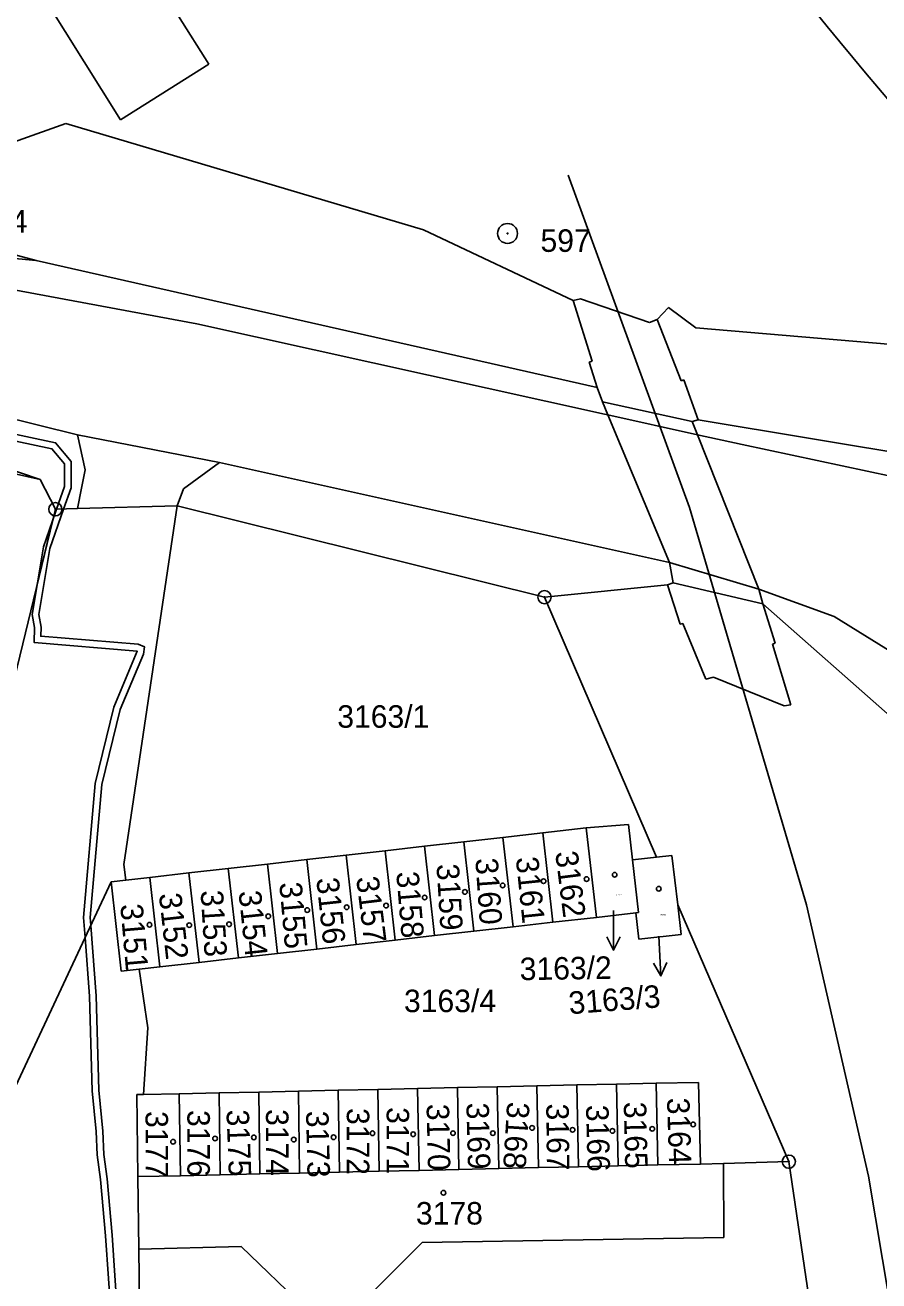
# Model space of a CAD drawing. Extents: x -735092 to -733385, y -1122435 to -1118992.
# Drawn here: x -734445.9 to -734381.4, y -1120165.2 to -1120070.4 of the extents above; entities that cross this region are included whole.
import ezdxf

# ---------------------------------------------------------------- set-up
doc = ezdxf.new("R2010")
doc.units = 0
for name, color, linetype in [('Vrstva 1', 7, 'Continuous'), ('Vrstva 10', 7, 'Continuous'), ('Vrstva 16', 7, 'Continuous'), ('Vrstva 17', 7, 'Continuous'), ('Vrstva 18', 7, 'Continuous'), ('Vrstva 19', 7, 'Continuous'), ('Vrstva 25', 7, 'Continuous'), ('Vrstva 27', 7, 'Continuous'), ('Vrstva 4', 7, 'Continuous')]:
    doc.layers.add(name, color=color, linetype=linetype)

msp = doc.modelspace()

# ---------------------------------------------------------------- linework, layer by layer
at = {"layer": 'Vrstva 1'}
for points in [[(-734459.57, -1120044.15), (-734438.66, -1120077.54)], [(-734436.56, -1120066.05), (-734431.98, -1120073.34)], [(-734438.66, -1120077.54), (-734431.98, -1120073.34)], [(-734451.69, -1120087.53), (-734445.03, -1120088.16)], [(-734445.03, -1120088.16), (-734402.65, -1120097.75)], [(-734451.59, -1120089.48), (-734432.9, -1120092.95)], [(-734432.9, -1120092.95), (-734402.11, -1120099.76)], [(-734402.65, -1120097.75), (-734402.26, -1120098.83)], [(-734450.98, -1120099.09), (-734441.92, -1120101.33)], [(-734402.26, -1120098.83), (-734395.48, -1120100.32)], [(-734402.11, -1120099.76), (-734401.85, -1120099.82)], [(-734401.85, -1120099.82), (-734395.08, -1120101.32)], [(-734395.48, -1120100.32), (-734395.03, -1120100.19)], [(-734395.03, -1120100.19), (-734377.92, -1120103.05)], [(-734441.92, -1120101.33), (-734431.18, -1120103.41)], [(-734395.08, -1120101.32), (-734391.71, -1120102.07)], [(-734391.71, -1120102.07), (-734378.49, -1120104.89)], [(-734450.69, -1120102.69), (-734444.72, -1120104.71)], [(-734431.18, -1120103.41), (-734397.21, -1120110.97)], [(-734444.72, -1120104.71), (-734443.58, -1120106.95)], [(-734441.91, -1120106.9), (-734434.38, -1120106.7)], [(-734438.42, -1120133.78), (-734434.38, -1120106.7)], [(-734434.38, -1120106.7), (-734406.64, -1120113.59)], [(-734449.99, -1120133.29), (-734443.58, -1120106.95)], [(-734443.58, -1120106.95), (-734441.91, -1120106.9)], [(-734397.21, -1120110.97), (-734390.44, -1120112.99)], [(-734397.35, -1120112.65), (-734396.92, -1120112.5)], [(-734396.92, -1120112.5), (-734390.15, -1120114.08)], [(-734406.64, -1120113.59), (-734397.35, -1120112.65)], [(-734390.44, -1120112.99), (-734384.75, -1120115.04)], [(-734406.64, -1120113.59), (-734398.18, -1120133.23)], [(-734390.15, -1120114.08), (-734380.11, -1120122.95)], [(-734384.75, -1120115.04), (-734379.59, -1120118.25)], [(-734409.78, -1120131.73), (-734406.77, -1120131.39)], [(-734406.77, -1120131.39), (-734403.49, -1120131.02)], [(-734406.77, -1120131.39), (-734406.01, -1120138.14)], [(-734403.49, -1120131.02), (-734400.29, -1120130.75)], [(-734403.49, -1120131.02), (-734402.72, -1120137.77)], [(-734400.29, -1120130.75), (-734399.99, -1120133.43)], [(-734418.67, -1120132.74), (-734415.7, -1120132.4)], [(-734415.7, -1120132.4), (-734412.74, -1120132.07)], [(-734415.7, -1120132.4), (-734414.94, -1120139.15)], [(-734412.74, -1120132.07), (-734409.78, -1120131.73)], [(-734412.74, -1120132.07), (-734411.97, -1120138.82)], [(-734409.78, -1120131.73), (-734409.01, -1120138.48)], [(-734427.57, -1120133.75), (-734424.59, -1120133.41)], [(-734424.59, -1120133.41), (-734421.63, -1120133.07)], [(-734424.59, -1120133.41), (-734423.83, -1120140.16)], [(-734421.63, -1120133.07), (-734418.67, -1120132.74)], [(-734421.63, -1120133.07), (-734420.87, -1120139.82)], [(-734418.67, -1120132.74), (-734417.91, -1120139.49)], [(-734399.99, -1120133.43), (-734398.18, -1120133.23)], [(-734398.18, -1120133.23), (-734397.01, -1120133.1)], [(-734397.01, -1120133.1), (-734396.58, -1120136.83)], [(-734438.42, -1120133.78), (-734438.25, -1120134.95)], [(-734433.49, -1120134.42), (-734430.53, -1120134.08)], [(-734430.53, -1120134.08), (-734427.57, -1120133.75)], [(-734430.53, -1120134.08), (-734429.76, -1120140.83)], [(-734427.57, -1120133.75), (-734426.8, -1120140.5)], [(-734399.99, -1120133.43), (-734399.54, -1120137.41)], [(-734458.68, -1120176.34), (-734439.36, -1120135.08)], [(-734439.36, -1120135.08), (-734438.25, -1120134.95)], [(-734439.36, -1120135.08), (-734438.6, -1120141.83)], [(-734438.25, -1120134.95), (-734436.45, -1120134.75)], [(-734436.45, -1120134.75), (-734433.49, -1120134.42)], [(-734436.45, -1120134.75), (-734435.69, -1120141.5)], [(-734433.49, -1120134.42), (-734432.73, -1120141.17)], [(-734396.58, -1120136.83), (-734388.19, -1120156.22)], [(-734396.58, -1120136.83), (-734396.33, -1120139.06)], [(-734409.01, -1120138.48), (-734406.01, -1120138.14)], [(-734406.01, -1120138.14), (-734402.72, -1120137.77)], [(-734402.72, -1120137.77), (-734399.74, -1120137.43)], [(-734399.74, -1120137.43), (-734399.54, -1120137.41)], [(-734399.74, -1120137.43), (-734399.51, -1120139.42)], [(-734414.94, -1120139.15), (-734411.97, -1120138.82)], [(-734411.97, -1120138.82), (-734409.01, -1120138.48)], [(-734399.51, -1120139.42), (-734396.33, -1120139.06)], [(-734423.83, -1120140.16), (-734420.87, -1120139.82)], [(-734420.87, -1120139.82), (-734417.91, -1120139.49)], [(-734417.91, -1120139.49), (-734414.94, -1120139.15)], [(-734432.73, -1120141.17), (-734429.76, -1120140.83)], [(-734429.76, -1120140.83), (-734426.8, -1120140.5)], [(-734426.8, -1120140.5), (-734423.83, -1120140.16)], [(-734438.6, -1120141.83), (-734437.25, -1120141.68)], [(-734437.25, -1120141.68), (-734435.69, -1120141.5)], [(-734437.25, -1120141.68), (-734436.59, -1120146.12)], [(-734435.69, -1120141.5), (-734432.73, -1120141.17)], [(-734436.93, -1120151.15), (-734436.59, -1120146.12)], [(-734407.21, -1120150.5), (-734404.2, -1120150.43)], [(-734404.2, -1120150.43), (-734401.2, -1120150.37)], [(-734404.2, -1120150.43), (-734404.08, -1120156.61)], [(-734401.2, -1120150.37), (-734398.2, -1120150.3)], [(-734401.2, -1120150.37), (-734401.07, -1120156.54)], [(-734398.2, -1120150.3), (-734395, -1120150.23)], [(-734398.2, -1120150.3), (-734398.07, -1120156.47)], [(-734395, -1120150.23), (-734394.86, -1120156.4)], [(-734437.42, -1120151.16), (-734436.93, -1120151.15)], [(-734437.42, -1120151.16), (-734437.35, -1120157.35)], [(-734436.93, -1120151.15), (-734434.22, -1120151.09)], [(-734434.22, -1120151.09), (-734431.22, -1120151.02)], [(-734434.22, -1120151.09), (-734434.14, -1120157.28)], [(-734431.22, -1120151.02), (-734428.22, -1120150.96)], [(-734431.22, -1120151.02), (-734431.14, -1120157.21)], [(-734428.22, -1120150.96), (-734425.22, -1120150.89)], [(-734428.22, -1120150.96), (-734428.13, -1120157.14)], [(-734425.22, -1120150.89), (-734422.22, -1120150.83)], [(-734425.22, -1120150.89), (-734425.13, -1120157.08)], [(-734422.22, -1120150.83), (-734419.22, -1120150.76)], [(-734422.22, -1120150.83), (-734422.12, -1120157.01)], [(-734419.22, -1120150.76), (-734416.22, -1120150.7)], [(-734419.22, -1120150.76), (-734419.12, -1120156.94)], [(-734416.22, -1120150.7), (-734413.21, -1120150.63)], [(-734416.22, -1120150.7), (-734416.11, -1120156.88)], [(-734413.21, -1120150.63), (-734410.21, -1120150.56)], [(-734413.21, -1120150.63), (-734413.1, -1120156.81)], [(-734410.21, -1120150.56), (-734407.21, -1120150.5)], [(-734410.21, -1120150.56), (-734410.1, -1120156.74)], [(-734407.21, -1120150.5), (-734407.09, -1120156.67)], [(-734428.13, -1120157.14), (-734425.13, -1120157.08)], [(-734425.13, -1120157.08), (-734422.12, -1120157.01)], [(-734422.12, -1120157.01), (-734419.12, -1120156.94)], [(-734419.12, -1120156.94), (-734416.11, -1120156.88)], [(-734416.11, -1120156.88), (-734413.1, -1120156.81)], [(-734413.1, -1120156.81), (-734410.1, -1120156.74)], [(-734410.1, -1120156.74), (-734407.09, -1120156.67)], [(-734407.09, -1120156.67), (-734404.08, -1120156.61)], [(-734404.08, -1120156.61), (-734401.07, -1120156.54)], [(-734401.07, -1120156.54), (-734398.07, -1120156.47)], [(-734398.07, -1120156.47), (-734394.86, -1120156.4)], [(-734394.86, -1120156.4), (-734393.13, -1120156.36)], [(-734393.13, -1120156.36), (-734388.19, -1120156.22)], [(-734388.19, -1120156.22), (-734385.85, -1120172.09)], [(-734437.35, -1120157.35), (-734434.14, -1120157.28)], [(-734437.35, -1120157.35), (-734437.28, -1120162.84)], [(-734434.14, -1120157.28), (-734431.14, -1120157.21)], [(-734431.14, -1120157.21), (-734428.13, -1120157.14)], [(-734437.28, -1120162.84), (-734437.16, -1120173.21)]]:
    msp.add_lwpolyline(points, dxfattribs=at)
at = {"layer": 'Vrstva 10'}
for points in [[(-734395.69, -1120106.82), (-734404.86, -1120081.71)], [(-734386.85, -1120136.82), (-734395.69, -1120106.82)], [(-734382.16, -1120157.32), (-734386.85, -1120136.82)], [(-734377.94, -1120182.5), (-734382.16, -1120157.32)]]:
    msp.add_lwpolyline(points, dxfattribs=at)
msp.add_arc((-734055.501, -1119800.285), 426.341, 214.45108, 220.95553, dxfattribs=at)
at = {"layer": 'Vrstva 25'}
for points in [[(-734401.43, -1120137.25), (-734401.43, -1120140.25)], [(-734400.931, -1120139.25), (-734401.43, -1120140.25), (-734401.93, -1120139.25)], [(-734398.01, -1120139.2), (-734397.848, -1120142.195)], [(-734397.403, -1120141.17), (-734397.848, -1120142.195), (-734398.401, -1120141.224)]]:
    msp.add_lwpolyline(points, dxfattribs=at)
for centre, radius in [((-734409.43, -1120086.12), 0.75), ((-734409.43, -1120086.12), 0.032), ((-734443.58, -1120106.95), 0.499), ((-734443.58, -1120106.95), 0.0312), ((-734406.64, -1120113.59), 0.5), ((-734406.64, -1120113.59), 0.0316), ((-734409.8, -1120135.36), 0.174), ((-734406.71, -1120135.04), 0.174), ((-734403.46, -1120134.88), 0.174), ((-734401.34, -1120134.55), 0.175), ((-734415.69, -1120136.27), 0.175), ((-734412.65, -1120135.85), 0.175), ((-734398.01, -1120135.61), 0.175), ((-734424.56, -1120137.22), 0.174), ((-734421.58, -1120137.01), 0.174), ((-734418.6, -1120136.88), 0.175), ((-734436.47, -1120138.33), 0.174), ((-734430.46, -1120138.29), 0.174), ((-734427.5, -1120137.69), 0.175), ((-734433.47, -1120138.36), 0.174), ((-734395.41, -1120153.41), 0.174), ((-734428.59, -1120154.39), 0.175), ((-734422.57, -1120154.38), 0.174), ((-734419.63, -1120154.08), 0.175), ((-734416.56, -1120154.15), 0.175), ((-734413.55, -1120154.07), 0.174), ((-734410.54, -1120154.07), 0.175), ((-734407.58, -1120153.67), 0.174), ((-734404.52, -1120153.82), 0.174), ((-734401.51, -1120153.9), 0.174), ((-734398.5, -1120153.74), 0.174), ((-734434.69, -1120154.72), 0.174), ((-734431.52, -1120154.47), 0.174), ((-734425.58, -1120154.55), 0.175), ((-734388.19, -1120156.22), 0.499), ((-734388.19, -1120156.22), 0.0312), ((-734414.27, -1120158.57), 0.175)]:
    msp.add_circle(centre, radius, dxfattribs=at)
at = {"layer": 'Vrstva 27'}
for points in [[(-734474.85, -1120093.62), (-734475.11, -1120094.82), (-734475.14, -1120095.33), (-734469.55, -1120095.67), (-734460.15, -1120097.79), (-734458.46, -1120098.76), (-734443.56, -1120101.92), (-734442.39, -1120103.34), (-734442.39, -1120105.32), (-734442.96, -1120106.93)], [(-734439.35, -1120168.27), (-734439.79, -1120161.82), (-734440.17, -1120157.57), (-734440.42, -1120155.71), (-734440.49, -1120153.95), (-734440.81, -1120150.87), (-734441, -1120143.71), (-734441.33, -1120139.3), (-734441.45, -1120137.78), (-734440.57, -1120127.65), (-734439.16, -1120121.9), (-734437.39, -1120117.67), (-734445.19, -1120117), (-734445.16, -1120115.89), (-734445.33, -1120114.9), (-734444.93, -1120112.5), (-734443.79, -1120107.82), (-734443.49, -1120106.95), (-734442.89, -1120105.24), (-734442.89, -1120103.52), (-734443.84, -1120102.38), (-734458.64, -1120099.24)], [(-734442.96, -1120106.93), (-734444, -1120109.91), (-734444.83, -1120114.9), (-734444.66, -1120115.85), (-734444.68, -1120116.54), (-734437.33, -1120117.15), (-734436.85, -1120117.33), (-734436.92, -1120117.89), (-734438.68, -1120122.06), (-734440.07, -1120127.73), (-734440.95, -1120137.78), (-734440.9, -1120138.38), (-734440.5, -1120143.69), (-734440.31, -1120150.83), (-734439.99, -1120153.91), (-734439.92, -1120155.67), (-734439.67, -1120157.51), (-734439.29, -1120161.78), (-734438.85, -1120168.23)], [(-734443.79, -1120107.82), (-734444.93, -1120112.5), (-734444.48, -1120109.79), (-734443.79, -1120107.82)]]:
    msp.add_lwpolyline(points, dxfattribs=at)
at = {"layer": 'Vrstva 4'}
for points in [[(-734450.36, -1120080.5), (-734442.78, -1120077.81)], [(-734442.78, -1120077.81), (-734415.78, -1120085.84)], [(-734415.78, -1120085.84), (-734404.47, -1120091.19)], [(-734451.82, -1120086.36), (-734445.03, -1120088.16)], [(-734404.47, -1120091.19), (-734403.93, -1120091.06)], [(-734404.47, -1120091.19), (-734403.05, -1120095.77)], [(-734403.93, -1120091.06), (-734398.71, -1120092.85)], [(-734398.71, -1120092.85), (-734398.13, -1120092.63)], [(-734398.13, -1120092.63), (-734397.28, -1120091.71)], [(-734398.13, -1120092.63), (-734396.32, -1120097.24)], [(-734397.28, -1120091.71), (-734395.22, -1120093.24)], [(-734395.22, -1120093.24), (-734373.86, -1120095.06)], [(-734403.26, -1120095.84), (-734403.05, -1120095.77)], [(-734403.26, -1120095.84), (-734402.65, -1120097.75)], [(-734396.32, -1120097.24), (-734396.12, -1120097.17)], [(-734396.12, -1120097.17), (-734395.03, -1120100.19)], [(-734402.26, -1120098.83), (-734401.85, -1120099.82)], [(-734401.85, -1120099.82), (-734397.21, -1120110.97)], [(-734395.48, -1120100.32), (-734395.08, -1120101.32)], [(-734441.92, -1120101.33), (-734441.33, -1120103.98)], [(-734395.08, -1120101.32), (-734390.44, -1120112.99)], [(-734450.79, -1120103.35), (-734444.72, -1120104.71)], [(-734441.6, -1120105.35), (-734441.33, -1120103.98)], [(-734433.9, -1120105.4), (-734431.18, -1120103.41)], [(-734441.91, -1120106.9), (-734441.6, -1120105.35)], [(-734434.38, -1120106.7), (-734433.9, -1120105.4)], [(-734397.21, -1120110.97), (-734396.92, -1120112.5)], [(-734397.35, -1120112.65), (-734396.39, -1120115.63)], [(-734390.44, -1120112.99), (-734390.15, -1120114.08)], [(-734390.15, -1120114.08), (-734389.23, -1120117.07)], [(-734396.39, -1120115.63), (-734396.2, -1120115.57)], [(-734396.2, -1120115.57), (-734394.46, -1120119.77)], [(-734389.42, -1120117.13), (-734389.23, -1120117.07)], [(-734389.42, -1120117.13), (-734388.03, -1120121.73)], [(-734394.46, -1120119.77), (-734393.87, -1120119.64)], [(-734393.87, -1120119.64), (-734388.54, -1120121.8)], [(-734388.54, -1120121.8), (-734388.03, -1120121.73)], [(-734393.13, -1120156.36), (-734393.1, -1120161.94)], [(-734437.28, -1120162.84), (-734429.54, -1120162.63), (-734424.75, -1120167.27), (-734420.77, -1120167.21), (-734415.87, -1120162.33), (-734393.1, -1120161.94)]]:
    msp.add_lwpolyline(points, dxfattribs=at)

# ---------------------------------------------------------------- texts
at = {"layer": 'Vrstva 16'}
for s, rotation, p in [('3163/2', 0.90001, (-734408.499, -1120142.519)), ('3163/3', 4.40004, (-734404.755, -1120145.091))]:
    msp.add_text(s, height=1.7, rotation=rotation, dxfattribs=at).set_placement(p)
at = {"layer": 'Vrstva 17'}
for s, p in [('1774', (-734450.75, -1120086.05)), ('597', (-734406.94, -1120087.51))]:
    msp.add_text(s, height=1.7, dxfattribs=at).set_placement(p)
at = {"layer": 'Vrstva 18'}
for s, p in [('3163/1', (-734422.29, -1120123.45)), ('3163/4', (-734417.25, -1120144.93))]:
    msp.add_text(s, height=1.7, dxfattribs=at).set_placement(p)
at = {"layer": 'Vrstva 19'}
for s, rotation, p in [('3160', 274.00218, (-734411.867, -1120133.335)), ('3161', 275.90219, (-734408.811, -1120133.268)), ('3162', 277.20221, (-734405.837, -1120132.853)), ('3158', 274.80219, (-734417.844, -1120134.362)), ('3159', 273.50218, (-734414.799, -1120133.767)), ('3155', 275.10219, (-734426.674, -1120135.171)), ('3156', 276.1022, (-734423.88, -1120134.837)), ('3157', 277.0022, (-734420.868, -1120134.764)), ('3152', 276.4022, (-734435.769, -1120136.006)), ('3153', 273.60217, (-734432.618, -1120135.757)), ('3154', 276.00219, (-734429.751, -1120135.817)), ('3151', 275.00219, (-734438.684, -1120136.811)), ('3175', 272.10216, (-734430.663, -1120152.312)), ('3174', 270.00215, (-734427.671, -1120152.25)), ('3172', 270.00215, (-734421.571, -1120152.17)), ('3171', 270.00215, (-734418.561, -1120152.1)), ('3170', 271.20216, (-734415.546, -1120151.865)), ('3169', 271.50216, (-734412.545, -1120151.784)), ('3168', 266.50212, (-734409.453, -1120151.671)), ('3167', 270.60215, (-734406.508, -1120151.837)), ('3166', 271.40216, (-734403.506, -1120151.945)), ('3165', 271.30216, (-734400.656, -1120151.715)), ('3164', 271.80216, (-734397.394, -1120151.413)), ('3177', 270.00215, (-734436.771, -1120152.4)), ('3176', 270.00215, (-734433.611, -1120152.32)), ('3173', 271.40216, (-734424.656, -1120152.395))]:
    msp.add_text(s, height=1.7, rotation=rotation, dxfattribs=at).set_placement(p)
for s, height, p in [('3163/2', 0.1, (-734401.23, -1120136.14)), ('3163/3', 0.1, (-734397.89, -1120137.61)), ('3178', 1.7, (-734416.35, -1120160.97))]:
    msp.add_text(s, height=height, dxfattribs=at).set_placement(p)

doc.saveas('drawing.dxf')
